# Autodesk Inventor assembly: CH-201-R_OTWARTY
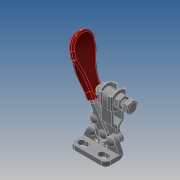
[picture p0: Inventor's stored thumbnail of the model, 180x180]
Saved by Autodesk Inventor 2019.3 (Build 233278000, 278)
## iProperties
Company: ·L?¤¤?
Created: 2010-06
Part Number: CH-201-R_OTWARTY
Material: Ogólny
Description: STEP AP203
Document SubType Name: Assembly
Designer: CADENGINEERING4
Sending System: SolidWorks 2005179
Preprocessor: SwSTEP 2.0
Title: CH-201-R.STEP
Author: ·L?¥Î?
Revision Number: ANY
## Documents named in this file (9)
- E:\STRONA\Horizontal toggle clamp\CH-201-R\CH-201-R_OTWARTY.iam
- E:\STRONA\Horizontal toggle clamp\CH-201-R\201-02___.ipt
- E:\STRONA\Horizontal toggle clamp\CH-201-R\201-06___.ipt
- E:\STRONA\Horizontal toggle clamp\CH-201-R\CH-SA-042007___.ipt
- E:\STRONA\Horizontal toggle clamp\CH-201-R\M4___.ipt
- E:\STRONA\Horizontal toggle clamp\CH-201-R\201-A-04___.ipt
- E:\STRONA\Horizontal toggle clamp\CH-201-R\CH-FW-080___.ipt
- E:\STRONA\Horizontal toggle clamp\CH-201-R\201-R-01___.ipt
- E:\STRONA\Horizontal toggle clamp\CH-201-R\201-03___.iam
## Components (14 placed, 14 different names)
1. 201-02_??_1 — Równoległe:1, Zestawiające:5, Zestawiające:7, Zestawiające:9, Zestawiające:25, Zestawiające:26, Zestawiające:27
2. 201-06_??_2 — Zestawiające:19, Zestawiające:20
3. CH-SA-042007_??_3 — Równoległe:2, Zestawiające:1, Zestawiające:2, Zestawiające:3, Zestawiające:4, Zestawiające:9
4. 201-06_??_4 — Zestawiające:15, Zestawiające:16
5. M4_??_5 — Równoległe:2, Zestawiające:2, Zestawiające:6
6. 201-A-04_??_6 — Zestawiające:10, Zestawiające:11, Zestawiające:12, Zestawiające:13, Zestawiające:18
7. CH-FW-080_??_7 — Równoległe:1, Równoległe:3, Zestawiające:1, Zestawiające:5, Zestawiające:6
8. M4_??_8 — Zestawiające:4, Zestawiające:8
9. 201-06_??_9 — Zestawiające:23, Zestawiające:24, Zestawiające:26
10. CH-FW-080_??_10 — Równoległe:3, Zestawiające:3, Zestawiające:7, Zestawiające:8
11. 201-R-01_??_11 — Zestawiające:13, Zestawiające:14, Zestawiające:16, Zestawiające:23, Zestawiające:24, Zestawiające:25, Przejściowe:1
12. 201-06_??_12 — Zestawiające:21, Zestawiające:22, Zestawiające:27
13. 201-A-04_??_13 — Zestawiające:10, Zestawiające:11, Zestawiające:12, Zestawiające:14, Zestawiające:15, Zestawiające:17
14. 201-03_??_14 [sub-assembly] — Zestawiające:17, Zestawiające:18, Zestawiające:19, Zestawiające:20, Zestawiające:21, Zestawiające:22, Przejściowe:1
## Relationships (31: Mate 27, Flush 3, Transitional 1)
- Równoległe:1 [Flush]: 201-02_??_1 ↔ CH-FW-080_??_7
- Równoległe:2 [Flush]: CH-SA-042007_??_3 ↔ M4_??_5
- Równoległe:3 [Flush]: CH-FW-080_??_7 ↔ CH-FW-080_??_10
- Zestawiające:1 [Mate]: CH-SA-042007_??_3 ↔ CH-FW-080_??_7
- Zestawiające:2 [Mate]: CH-SA-042007_??_3 ↔ M4_??_5
- Zestawiające:3 [Mate]: CH-SA-042007_??_3 ↔ CH-FW-080_??_10
- Zestawiające:4 [Mate]: CH-SA-042007_??_3 ↔ M4_??_8
- Zestawiające:5 [Mate]: 201-02_??_1 ↔ CH-FW-080_??_7
- Zestawiające:6 [Mate]: M4_??_5 ↔ CH-FW-080_??_7
- Zestawiające:7 [Mate]: 201-02_??_1 ↔ CH-FW-080_??_10
- Zestawiające:8 [Mate]: M4_??_8 ↔ CH-FW-080_??_10
- Zestawiające:9 [Mate]: 201-02_??_1 ↔ CH-SA-042007_??_3
- Zestawiające:10 [Mate]: 201-A-04_??_6 ↔ 201-A-04_??_13
- Zestawiające:11 [Mate]: 201-A-04_??_6 ↔ 201-A-04_??_13
- Zestawiające:12 [Mate]: 201-A-04_??_6 ↔ 201-A-04_??_13
- Zestawiające:13 [Mate]: 201-A-04_??_6 ↔ 201-R-01_??_11
- Zestawiające:14 [Mate]: 201-R-01_??_11 ↔ 201-A-04_??_13
- Zestawiające:15 [Mate]: 201-06_??_4 ↔ 201-A-04_??_13
- Zestawiające:16 [Mate]: 201-06_??_4 ↔ 201-R-01_??_11
- Zestawiające:17 [Mate]: 201-A-04_??_13 ↔ 201-03_??_14
- Zestawiające:18 [Mate]: 201-A-04_??_6 ↔ 201-03_??_14
- Zestawiające:19 [Mate]: 201-06_??_2 ↔ 201-03_??_14
- Zestawiające:20 [Mate]: 201-06_??_2 ↔ 201-03_??_14
- Zestawiające:21 [Mate]: 201-06_??_12 ↔ 201-03_??_14
- Zestawiające:22 [Mate]: 201-06_??_12 ↔ 201-03_??_14
- Zestawiające:23 [Mate]: 201-06_??_9 ↔ 201-R-01_??_11
- Zestawiające:24 [Mate]: 201-06_??_9 ↔ 201-R-01_??_11
- Zestawiające:25 [Mate]: 201-02_??_1 ↔ 201-R-01_??_11
- Zestawiające:26 [Mate]: 201-02_??_1 ↔ 201-06_??_9
- Zestawiające:27 [Mate]: 201-02_??_1 ↔ 201-06_??_12
- Przejściowe:1 [Transitional]: 201-R-01_??_11 ↔ 201-03_??_14
